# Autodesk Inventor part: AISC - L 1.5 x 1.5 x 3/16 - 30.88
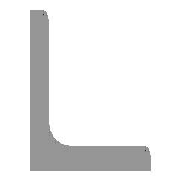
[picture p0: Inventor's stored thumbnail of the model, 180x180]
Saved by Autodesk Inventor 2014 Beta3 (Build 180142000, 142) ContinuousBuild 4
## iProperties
_CCFamilyMember: 5
_CCFamilyDisplayName: ANSI L (Equal angles) - Angle Steel
_FrameMemberDoc: Frame Member File
_Version: 15.0.0
_GetPNFromCC: 1
Created: 2010-11
Part Number: AISC - L 1.5 x 1.5 x 3/16 - 30.88
Material: Steel, Mild
Description: Angle Steel
Document SubType Name: Modeling
Standard: ANSI
Designer: Beta-8540w
Standards Organization: ANSI
Language: en-US
Size Designation: L 1.5 x 1.5 x 3/16
Categories: <MemberInstance><Categories><Category DisplayName="Structural Shapes" InternalName="089c4875-fa83-4c05-b084-43b9cc11f5ed" Mnemonic="GRDR"><CategoryParameter Dis
Stock Number: L 1.5 x 1.5 x 3/16
Density: 7.86 g/cm^3
Appearance: Steel
IsCustomPart: 1
G_L: 30.880 in
G_W: 1.500 in
G_H: 1.500 in
+3B2E30B5-4963-484D-8D95-D946A704ABD9+CUTDETAIL1: Cut
Author: Beta-8540w
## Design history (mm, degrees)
node "Start plane"
node "End plane"
sketch "Sketch"
  geometry: L1 (38.1, 0)-(0, 0); L2 (0, 0)-(0, 38.1); L3 (0, 38.1)-(2.476, 38.1); L4 (4.762, 35.814)-(4.762, 9.589); L5 (9.588, 4.763)-(35.814, 4.763); L6 (38.1, 2.477)-(38.1, 0); L7 (0, -11.041)-(0, 31.538); L8 (-11.041, 0)-(31.538, 0); L9 (0, 48.496)-(0, -20.964) reference; L10 (-20.964, 0)-(48.496, 0) reference; A1 r 4.826 centre (9.588, 9.589) between (4.762, 9.589) and (9.588, 4.763); A2 r 2.286 centre (2.476, 35.814) between (4.762, 35.814) and (2.476, 38.1); A3 r 2.286 centre (35.814, 2.477) between (38.1, 2.477) and (35.814, 4.763); 3 further points
  constraints: 16 end point, 6 point on circle, 6 point on line, 6 tangent, 4 parallel, 3 centre point, 2 collinear, 1 equal radius, 1 horizontal, 1 perpendicular
  dimensions: "d0" = 38.1 distance between parallel lines of L6 L2 (= G_H); "d1" = 38.1 distance between parallel lines of L3 L1 (= G_H); "d2" = 4.7625 distance between parallel lines of L2 L4 (= G_T); "d3" = 4.7625 distance between parallel lines of L1 L5 (= G_T); "d10" = 0 distance between parallel lines of L7 L2 (computed from ex); "d11" = 0 distance between parallel lines of L8 L1 (computed from d10); "d14" = 4.826 radius of A1 (= G_IR); "d15" = 2.286 radius of A2 (= G_ER)
extrude "Body" new body sketch "Sketch" stored distance "d4" = 784.34465 (= G_L); taper "d5" = 0 deg
node "Driven Length"
  sketch "Sketch3"
    geometry: L1 (0, 0)-(10, 0) reference
    constraints: 2 end point, 1 horizontal
  workplane "Work Plane3"
  sketch "Sketch4"
    geometry: L1 (-2, 0)-(12, 0) reference; L2 (-2, 784.345)-(12, 784.345) reference
    dimensions: "d17" = 784.34465 distance between parallel lines of L1 L2 (derived)
workplane "Work Plane4"
split "Split1"
body "Solid1"
other parameters: "G_H" = 38.1 [user parameter; used in 2 equation terms], "G_T" = 4.7625 [user parameter; used in 2 equation terms], "G_ER" = 2.286 [user parameter; used in 1 equation term], "G_IR" = 4.826 [user parameter; used in 1 equation term], "G_L" = 784.34465 (= d17) [user parameter; used in 1 equation term], "ex" = 0 [user parameter; used in 1 equation term], "G_OFFSET_START" = 0 [user parameter; used in 1 equation term], "G_OFFSET_END" = -32.98927 [user parameter; used in 1 equation term], "d12" = 0 (computed from G_OFFSET_START), "d13" = 784.34465 (= G_OFFSET_END + B_L), "B_L" = 817.33392 [user parameter; used in 1 equation term], "d16" = 90 deg, "MAS" = 0.26787 [user parameter]
